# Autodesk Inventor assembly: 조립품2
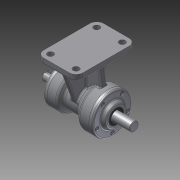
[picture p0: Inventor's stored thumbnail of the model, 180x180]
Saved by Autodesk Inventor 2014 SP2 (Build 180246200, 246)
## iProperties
Created: 2015-08
Part Number: 조립품2
Document SubType Name: Assembly
Designer: 이준우
Author: 이준우
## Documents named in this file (10)
- C:\Users\201-14\Desktop\450805V1041\조립품2.iam
- C:\Users\201-14\Desktop\450805V1041\본체.ipt
- C:\Users\201-14\Desktop\450805V1041\축.ipt
- C:\Users\201-14\Desktop\450805V1041\베어링 6203.ipt
- C:\Users\201-14\Desktop\450805V1041\베어링 6205.ipt
- C:\Users\201-14\Desktop\450805V1041\뒤커버.ipt
- C:\Users\201-14\Desktop\450805V1041\앞커버.ipt
- C:\Users\201-14\Desktop\450805V1041\오일실 .ipt
- 오일실 .ipt
- C:\Users\201-14\Desktop\450805V1041\M4x0.5.ipt
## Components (10 placed, 1 different names)
1. M4x0.5:1
2. M4x0.5:2
3. M4x0.5:3
4. M4x0.5:4
5. M4x0.5:5
6. M4x0.5:6
7. M4x0.5:7
8. M4x0.5:8
9. M4x0.5:9
10. M4x0.5:10
